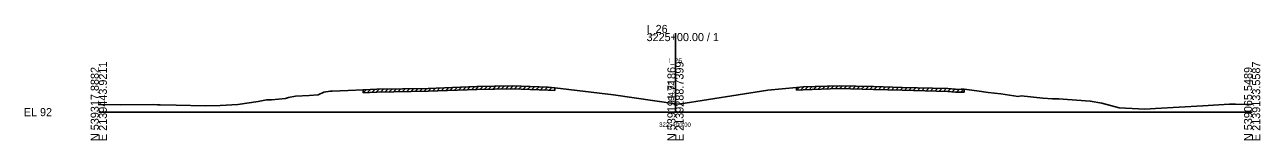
# Model space of a CAD drawing. Extents: x -13101 to 4803, y -924 to 22390.
# Drawn here: x 1974.3 to 2402.8, y 12490.3 to 12530.2 of the extents above; entities that cross this region are included whole.
import ezdxf

# ---------------------------------------------------------------- set-up
doc = ezdxf.new("R2010")
doc.units = 0
for name, color, linetype in [('RD_GPK_XS_Cell', 7, 'Continuous'), ('RD_XS_ExGround', 7, 'Continuous'), ('RD_XS_ExPaveRet', 7, 'Continuous'), ('RD_XS_TX_Baseline', 7, 'Continuous'), ('RD_XS_TX_Elev_EX', 7, 'Continuous'), ('RD_XS_TX_Station', 7, 'Continuous')]:
    doc.layers.add(name, color=color, linetype=linetype)

msp = doc.modelspace()

# ---------------------------------------------------------------- linework, layer by layer
at = {"layer": 'RD_GPK_XS_Cell'}
for p, q in [((2200, 12500), (2200, 12527.33)), ((2000, 12500), (2200, 12500)), ((2200, 12500), (2400, 12500))]:
    msp.add_line(p, q, dxfattribs=at)
at = {"layer": 'RD_XS_ExGround'}
msp.add_lwpolyline([(2000, 12502.66), (2007.55, 12502.55), (2019, 12502.6), (2020.39, 12502.56), (2021.34, 12502.53), (2026.82, 12502.41), (2036.85, 12502.15), (2042.05, 12502.27), (2048.19, 12502.6), (2055.3, 12503.71), (2058.2, 12504.2), (2059.87, 12504.3), (2064.78, 12504.75), (2065.81, 12505.04), (2068.21, 12505.49), (2072.95, 12505.8), (2076.1, 12506.01), (2078.07, 12506.93), (2080.29, 12507.26), (2080.95, 12507.22), (2086.48, 12507.49), (2091.71, 12507.68), (2096.43, 12507.9), (2114.25, 12508.19), (2131.16, 12508.8), (2143.39, 12509.1), (2155.82, 12508.63), (2158.2, 12508.45), (2178.51, 12505.94), (2200, 12502.92), (2201.16, 12502.75), (2232.01, 12507.63), (2241.93, 12508.56), (2244.24, 12508.69), (2256.78, 12509.11), (2268.64, 12508.8), (2278.58, 12508.55), (2294.5, 12508.12), (2297.08, 12507.94), (2298.43, 12507.87), (2299.05, 12507.9), (2300.19, 12507.93), (2304.56, 12507.35), (2308.44, 12506.84), (2312.9, 12506.34), (2318.9, 12505.41), (2319.96, 12505.58), (2327.38, 12504.78), (2330.75, 12504.54), (2332.96, 12504.55), (2336.02, 12504.39), (2343.89, 12503.83), (2347.88, 12503.08), (2353.89, 12501.47), (2360.65, 12501.1), (2362.84, 12501.08), (2366.48, 12501.29), (2382.91, 12502.23), (2392.14, 12502.71), (2393.09, 12502.76), (2394.29, 12502.79), (2398.75, 12502.68), (2400, 12502.78)], dxfattribs=at)
at = {"layer": 'RD_XS_ExPaveRet'}
for p, q in [((2133.71, 12507.86), (2134.74, 12508.89)), ((2135.21, 12507.9), (2136.24, 12508.92)), ((2136.71, 12507.93), (2137.74, 12508.96)), ((2138.21, 12507.97), (2139.24, 12508.99)), ((2139.71, 12508.01), (2140.74, 12509.03)), ((2141.21, 12508.04), (2142.24, 12509.07)), ((2142.71, 12508.08), (2143.72, 12509.08)), ((2144.21, 12508.07), (2145.18, 12509.03)), ((2145.71, 12508.01), (2146.68, 12508.97)), ((2147.21, 12507.95), (2148.18, 12508.92)), ((2249.43, 12507.86), (2250.46, 12508.9)), ((2250.93, 12507.91), (2251.96, 12508.95)), ((2252.43, 12507.96), (2253.46, 12509)), ((2253.93, 12508.01), (2254.96, 12509.05)), ((2255.43, 12508.06), (2256.46, 12509.1)), ((2256.93, 12508.1), (2257.9, 12509.08)), ((2258.43, 12508.07), (2259.4, 12509.04)), ((2259.93, 12508.03), (2260.9, 12509)), ((2261.43, 12507.99), (2262.4, 12508.96)), ((2262.93, 12507.95), (2263.9, 12508.92)), ((2264.43, 12507.91), (2265.4, 12508.89)), ((2091.71, 12506.68), (2092.76, 12507.73)), ((2091.71, 12506.68), (2091.71, 12507.68)), ((2091.71, 12506.68), (2096.43, 12506.9)), ((2093.21, 12506.75), (2094.26, 12507.8)), ((2094.71, 12506.82), (2095.76, 12507.87)), ((2096.21, 12506.89), (2097.24, 12507.91)), ((2096.43, 12506.9), (2114.25, 12507.19)), ((2097.71, 12506.92), (2098.73, 12507.94)), ((2099.21, 12506.95), (2100.23, 12507.96)), ((2100.71, 12506.97), (2101.73, 12507.99)), ((2102.21, 12506.99), (2103.23, 12508.01)), ((2103.71, 12507.02), (2104.73, 12508.04)), ((2105.21, 12507.04), (2106.23, 12508.06)), ((2106.71, 12507.07), (2107.73, 12508.09)), ((2108.21, 12507.09), (2109.23, 12508.11)), ((2109.71, 12507.12), (2110.73, 12508.13)), ((2111.21, 12507.14), (2112.23, 12508.16)), ((2112.71, 12507.17), (2113.73, 12508.18)), ((2114.21, 12507.19), (2115.25, 12508.23)), ((2114.25, 12507.19), (2131.16, 12507.8)), ((2115.71, 12507.24), (2116.75, 12508.28)), ((2117.21, 12507.3), (2118.25, 12508.34)), ((2118.71, 12507.35), (2119.75, 12508.39)), ((2120.21, 12507.41), (2121.25, 12508.44)), ((2121.71, 12507.46), (2122.75, 12508.5)), ((2123.21, 12507.51), (2124.25, 12508.55)), ((2124.71, 12507.57), (2125.75, 12508.6)), ((2126.21, 12507.62), (2127.25, 12508.66)), ((2127.71, 12507.67), (2128.75, 12508.71)), ((2129.21, 12507.73), (2130.25, 12508.77)), ((2130.71, 12507.78), (2131.74, 12508.81)), ((2131.16, 12507.8), (2143.39, 12508.1)), ((2132.21, 12507.82), (2133.24, 12508.85)), ((2143.39, 12508.1), (2155.82, 12507.63)), ((2148.71, 12507.9), (2149.68, 12508.86)), ((2150.21, 12507.84), (2151.18, 12508.81)), ((2151.71, 12507.79), (2152.68, 12508.75)), ((2153.21, 12507.73), (2154.18, 12508.7)), ((2154.71, 12507.68), (2155.68, 12508.64)), ((2155.82, 12507.63), (2158.2, 12507.45)), ((2156.21, 12507.6), (2157.14, 12508.53)), ((2158.2, 12508.45), (2158.2, 12507.45)), ((2241.93, 12507.56), (2242.99, 12508.62)), ((2241.93, 12507.56), (2241.93, 12508.56)), ((2241.93, 12507.56), (2244.24, 12507.69)), ((2243.43, 12507.64), (2244.48, 12508.7)), ((2244.24, 12507.69), (2256.78, 12508.11)), ((2244.93, 12507.71), (2245.96, 12508.75)), ((2246.43, 12507.76), (2247.46, 12508.8)), ((2247.93, 12507.81), (2248.96, 12508.85)), ((2256.78, 12508.11), (2268.64, 12507.8)), ((2265.93, 12507.87), (2266.9, 12508.85)), ((2267.43, 12507.83), (2268.4, 12508.81)), ((2268.64, 12507.8), (2278.58, 12507.55)), ((2268.93, 12507.79), (2269.9, 12508.77)), ((2270.43, 12507.76), (2271.4, 12508.73)), ((2271.93, 12507.72), (2272.9, 12508.69)), ((2273.43, 12507.68), (2274.4, 12508.66)), ((2274.93, 12507.64), (2275.9, 12508.62)), ((2276.43, 12507.6), (2277.4, 12508.58)), ((2277.93, 12507.57), (2278.9, 12508.54)), ((2278.58, 12507.55), (2294.5, 12507.12)), ((2279.43, 12507.53), (2280.4, 12508.5)), ((2280.93, 12507.49), (2281.9, 12508.46)), ((2282.43, 12507.45), (2283.4, 12508.42)), ((2283.93, 12507.41), (2284.9, 12508.38)), ((2285.43, 12507.37), (2286.4, 12508.34)), ((2286.93, 12507.33), (2287.9, 12508.3)), ((2288.43, 12507.28), (2289.4, 12508.26)), ((2289.93, 12507.24), (2290.9, 12508.22)), ((2291.43, 12507.2), (2292.4, 12508.18)), ((2292.93, 12507.16), (2293.9, 12508.14)), ((2294.43, 12507.12), (2295.36, 12508.06)), ((2294.5, 12507.12), (2297.08, 12506.94)), ((2295.93, 12507.02), (2296.86, 12507.96)), ((2297.08, 12506.94), (2298.43, 12506.87)), ((2297.43, 12506.92), (2298.37, 12507.87)), ((2298.43, 12506.87), (2299.05, 12506.9)), ((2298.93, 12506.89), (2299.96, 12507.93)), ((2299.05, 12506.9), (2300.19, 12506.93)), ((2300.19, 12507.93), (2300.19, 12506.93))]:
    msp.add_line(p, q, dxfattribs=at)

# ---------------------------------------------------------------- texts
at = {"layer": 'RD_GPK_XS_Cell'}
for s, p in [('3225+00.00 / 1', (2190, 12524.53)), ('I_26', (2190, 12527.33)), ('EL 92', (1974, 12498.6))]:
    msp.add_text(s, height=2.8, dxfattribs=at).set_placement(p)
for s, p in [('N 539317.8882', (2000, 12490)), ('E 2139443.9211', (2002.8, 12490)), ('N 539191.7186', (2200, 12490)), ('E 2139288.7399', (2202.8, 12490)), ('N 539065.5489', (2400, 12490)), ('E 2139133.5587', (2402.8, 12490))]:
    msp.add_text(s, height=2.8, rotation=90, dxfattribs=at).set_placement(p)
at = {"layer": 'RD_XS_TX_Baseline'}
msp.add_text('I_26', height=1.75, dxfattribs=at).set_placement((2197.6, 12516.92))
at = {"layer": 'RD_XS_TX_Elev_EX'}
msp.add_text('94.92', height=2, rotation=90, dxfattribs=at).set_placement((2199.5, 12503.92))
at = {"layer": 'RD_XS_TX_Station'}
msp.add_text('3225+00.00', height=1.5, dxfattribs=at).set_placement((2194.36, 12494.92))

doc.saveas('drawing.dxf')
